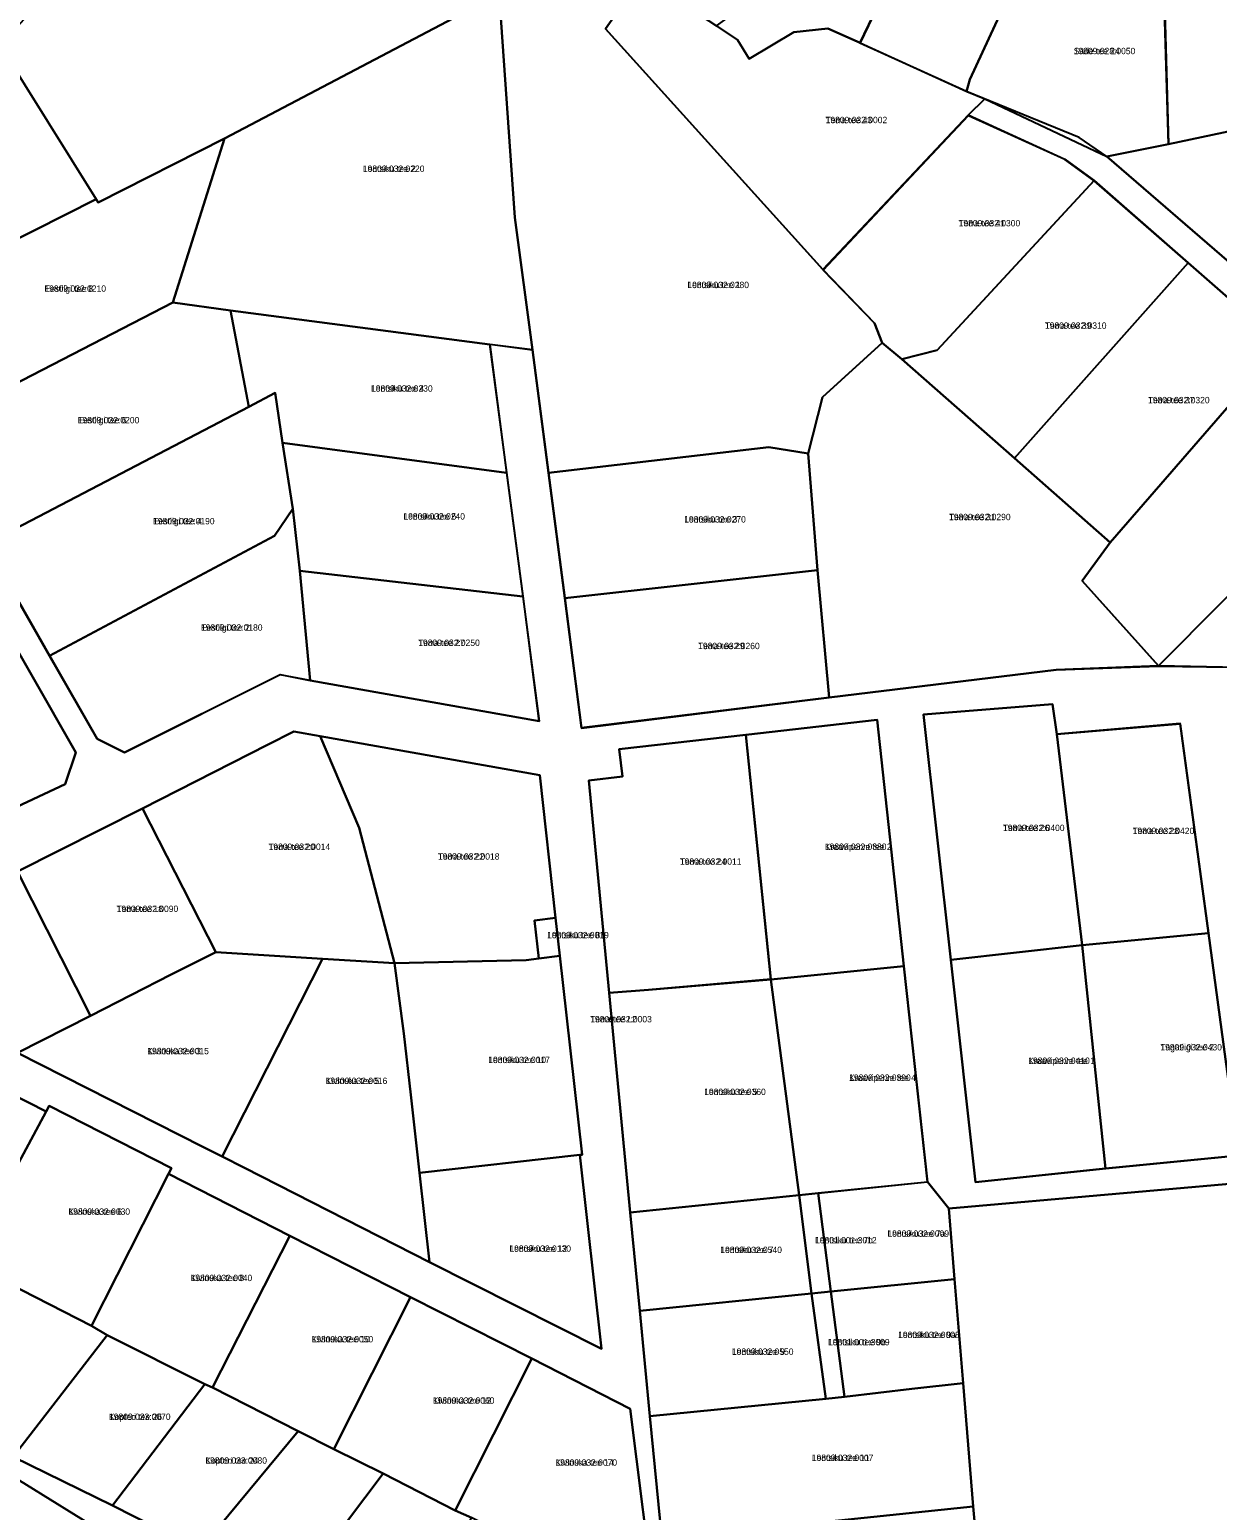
# Model space of a CAD drawing. Extents: x 516875 to 535633, y 6574491 to 6593094.
# Drawn here: x 521368.5 to 521648.2, y 6588311.2 to 6588659.7 of the extents above; entities that cross this region are included whole.
import ezdxf

# ---------------------------------------------------------------- set-up
doc = ezdxf.new("R2010")
doc.units = 0
for name, color, linetype in [('L_AADRESS', 7, 'Continuous'), ('PIIR', 7, 'Continuous'), ('TUNNUS', 7, 'Continuous')]:
    doc.layers.add(name, color=color, linetype=linetype)

msp = doc.modelspace()

# ---------------------------------------------------------------- linework, layer by layer
at = {"layer": 'PIIR'}
for points in [[(521413.29, 6588714.19), (521418.94, 6588723.37), (521421.81, 6588728.14), (521449.85, 6588699.7), (521477.52, 6588688.69), (521479.07, 6588668.07), (521414.43, 6588634.08), (521384.67, 6588618.99), (521384.19, 6588619.81), (521361.62, 6588655.9)], [(521555.15, 6588700.16), (521579.64, 6588689.1), (521564.06, 6588656.54), (521556.42, 6588659.95), (521548.45, 6588659.06), (521537.94, 6588652.79), (521535.14, 6588657.27), (521530.2, 6588660.59), (521540.06, 6588667.73)], [(521486.87, 6588584.33), (521482.75, 6588615.48), (521479.07, 6588668.07), (521477.52, 6588688.69), (521494.97, 6588682.17), (521512.17, 6588671.42), (521504.07, 6588659.84), (521555.23, 6588603.22), (521567.46, 6588590.61), (521569.21, 6588585.96), (521555.19, 6588573.17), (521551.79, 6588559.93), (521542.52, 6588561.47), (521490.64, 6588555.41)], [(521579.64, 6588689.1), (521603.77, 6588677.97), (521589.89, 6588647.97), (521589.09, 6588645.14), (521564.01, 6588656.5)], [(521589.89, 6588647.97), (521603.77, 6588677.97), (521616, 6588673.19), (521635.59, 6588669.68), (521636.61, 6588632.74), (521622.12, 6588629.84), (521615.58, 6588634.3), (521589.09, 6588645.14)], [(521635.57, 6588669.71), (521645.98, 6588675.4), (521650.36, 6588677.81), (521657.98, 6588660.01), (521686.54, 6588663.79), (521687.16, 6588643.42), (521662.53, 6588638.23), (521636.65, 6588632.7)], [(521512.66, 6588672.12), (521530.2, 6588660.59), (521535.14, 6588657.27), (521537.94, 6588652.79), (521548.45, 6588659.06), (521556.42, 6588659.95), (521564.06, 6588656.54), (521589.16, 6588645.12), (521593.39, 6588643.38), (521589.51, 6588639.54), (521555.23, 6588603.22), (521504.07, 6588659.84)], [(521402.26, 6588595.47), (521414.43, 6588634.08), (521479.07, 6588668.07), (521482.75, 6588615.48), (521486.87, 6588584.33), (521476.87, 6588585.59), (521415.82, 6588593.57)], [(521384.19, 6588619.81), (521304.11, 6588579.39), (521302.8, 6588580.8), (521290.73, 6588597.7), (521361.62, 6588655.9)], [(521636.61, 6588632.74), (521662.53, 6588638.23), (521687.16, 6588643.42), (521692.7, 6588638.85), (521675.78, 6588636.22), (521675.71, 6588630.06), (521652.69, 6588603.5), (521622.12, 6588629.84)], [(521573.84, 6588582.13), (521569.21, 6588585.96), (521567.46, 6588590.61), (521555.31, 6588603.1), (521589.52, 6588639.46), (521612.21, 6588629.17), (521619.16, 6588624.15), (521582.14, 6588584.26)], [(521336.74, 6588561.89), (521326.71, 6588564.3), (521315.63, 6588566.96), (521304.11, 6588579.39), (521384.19, 6588619.81), (521384.67, 6588618.99), (521414.43, 6588634.08), (521402.26, 6588595.47), (521343.03, 6588564.98)], [(521573.84, 6588582.13), (521582.14, 6588584.26), (521619.16, 6588624.15), (521641.26, 6588604.83), (521600.35, 6588558.85)], [(521600.35, 6588558.85), (521641.26, 6588604.83), (521663.3, 6588585.55), (521622.88, 6588538.98)], [(521343.03, 6588564.98), (521402.26, 6588595.47), (521415.82, 6588593.57), (521420.15, 6588570.94), (521358.14, 6588538.6)], [(521426.33, 6588574.19), (521420.15, 6588570.94), (521415.82, 6588593.57), (521476.87, 6588585.59), (521480.82, 6588555.43), (521428.08, 6588562.47)], [(521553.97, 6588532.47), (521551.79, 6588559.93), (521555.19, 6588573.17), (521569.21, 6588585.96), (521573.84, 6588582.13), (521600.35, 6588558.85), (521622.88, 6588538.98), (521616.28, 6588529.95), (521634.3, 6588509.94), (521610.2, 6588509), (521556.78, 6588502.53)], [(521616.28, 6588529.95), (521622.88, 6588538.98), (521663.3, 6588585.55), (521686.13, 6588565.57), (521664.39, 6588540.27), (521634.3, 6588509.94)], [(521358.14, 6588538.6), (521420.15, 6588570.94), (521426.33, 6588574.19), (521428.08, 6588562.47), (521430.45, 6588546.91), (521426.17, 6588540.56), (521373.18, 6588512.37)], [(521676.85, 6588510.03), (521656.9, 6588509.51), (521634.3, 6588509.94), (521664.39, 6588540.27), (521686.13, 6588565.57), (521711.04, 6588543.8), (521682.19, 6588513.73)], [(521430.45, 6588546.91), (521428.08, 6588562.47), (521480.82, 6588555.43), (521484.65, 6588526.32), (521432.15, 6588532.34)], [(521490.64, 6588555.41), (521542.52, 6588561.47), (521551.79, 6588559.93), (521553.97, 6588532.47), (521494.53, 6588525.92)], [(521384.42, 6588492.79), (521373.18, 6588512.37), (521426.17, 6588540.56), (521430.45, 6588546.91), (521432.15, 6588532.34), (521434.59, 6588506.53), (521427.53, 6588507.89), (521390.87, 6588489.57)], [(521432.15, 6588532.34), (521484.65, 6588526.32), (521488.51, 6588496.98), (521434.59, 6588506.53)], [(521494.53, 6588525.92), (521553.97, 6588532.47), (521556.78, 6588502.53), (521498.48, 6588495.36)], [(521324.69, 6588511.99), (521330.6, 6588513.8), (521336.2, 6588511.76), (521358.78, 6588525.59), (521379.42, 6588489.59), (521376.89, 6588482.13), (521349.03, 6588469.11)], [(521578.99, 6588498.53), (521585.38, 6588440.81), (521591.22, 6588388.52), (521621.86, 6588391.71), (521653.14, 6588394.78), (521646.07, 6588447.07), (521639.38, 6588496.37), (521610.38, 6588493.89), (521609.37, 6588500.98)], [(521609.35, 6588500.97), (521610.36, 6588493.91), (521616.34, 6588444.25), (521585.38, 6588440.81), (521578.99, 6588498.53)], [(521537.13, 6588493.76), (521568.05, 6588497.29), (521574.35, 6588439.3), (521543.04, 6588436.19)], [(521610.36, 6588493.91), (521639.38, 6588496.34), (521646.04, 6588447.07), (521616.34, 6588444.25)], [(521323.78, 6588440.31), (521365.66, 6588418.95), (521409.32, 6588396.82), (521413.81, 6588394.55), (521419.09, 6588391.88), (521462.63, 6588369.68), (521503.15, 6588349.24), (521498.02, 6588394.94), (521498.57, 6588394.91), (521494.88, 6588427.74), (521493.33, 6588441.71), (521492.34, 6588450.66), (521488.6, 6588484.27), (521436.92, 6588493.42), (521430.73, 6588494.52), (521424.55, 6588491.36), (521395.11, 6588476.42), (521365.67, 6588461.55)], [(521395.11, 6588476.42), (521424.55, 6588491.36), (521430.73, 6588494.52), (521436.92, 6588493.42), (521446.11, 6588471.83), (521454.43, 6588440.02), (521437.47, 6588441.06), (521412.32, 6588442.6)], [(521436.92, 6588493.42), (521488.6, 6588484.27), (521492.34, 6588450.66), (521487.39, 6588450.02), (521488.39, 6588441.08), (521485.39, 6588440.69), (521454.43, 6588440.02), (521446.11, 6588471.83)], [(521500.15, 6588482.97), (521508.09, 6588483.95), (521507.31, 6588490.34), (521537.16, 6588493.73), (521543.05, 6588436.21), (521514.23, 6588433.75), (521504.93, 6588433.03)], [(521365.67, 6588461.55), (521395.11, 6588476.42), (521412.32, 6588442.6), (521401.85, 6588437.31), (521382.85, 6588427.66)], [(521382.85, 6588427.66), (521365.66, 6588418.95), (521323.78, 6588440.31), (521365.67, 6588461.55)], [(521487.39, 6588450.02), (521492.34, 6588450.66), (521493.33, 6588441.71), (521488.39, 6588441.08)], [(521616.34, 6588444.25), (521646.04, 6588447.07), (521653.1, 6588394.78), (521621.84, 6588391.69)], [(521365.66, 6588418.95), (521382.85, 6588427.66), (521401.85, 6588437.31), (521412.32, 6588442.6), (521437.47, 6588441.06), (521413.81, 6588394.55), (521409.32, 6588396.82)], [(521585.38, 6588440.81), (521616.34, 6588444.25), (521621.84, 6588391.69), (521591.18, 6588388.5)], [(521437.47, 6588441.06), (521454.43, 6588440.02), (521456.63, 6588423.5), (521458.23, 6588409.01), (521460.27, 6588390.65), (521462.63, 6588369.68), (521419.09, 6588391.88), (521413.81, 6588394.55)], [(521454.43, 6588440.02), (521485.39, 6588440.69), (521488.39, 6588441.08), (521493.33, 6588441.71), (521494.88, 6588427.74), (521498.57, 6588394.91), (521498.02, 6588394.94), (521460.27, 6588390.65), (521458.23, 6588409.01), (521456.63, 6588423.5)], [(521543.04, 6588436.19), (521574.35, 6588439.3), (521579.88, 6588388.5), (521554.14, 6588385.88), (521549.7, 6588385.41)], [(521504.96, 6588433), (521514.21, 6588433.77), (521543.04, 6588436.19), (521549.7, 6588385.41), (521509.93, 6588381.33)], [(521320.13, 6588386.78), (521338.31, 6588422.41), (521372.42, 6588405.09), (521353.4, 6588369.85)], [(521364.61, 6588323.87), (521355.48, 6588328.35), (521318.72, 6588351.51), (521285.85, 6588399.49), (521285.39, 6588404.51), (521320.13, 6588386.78), (521353.4, 6588369.85), (521383.07, 6588354.68), (521386.74, 6588352.5)], [(521353.4, 6588369.85), (521372.42, 6588405.09), (521373.15, 6588406.46), (521401.93, 6588391.79), (521401.19, 6588390.42), (521383.07, 6588354.68)], [(521460.27, 6588390.65), (521498.02, 6588394.94), (521503.15, 6588349.24), (521462.63, 6588369.68)], [(521383.07, 6588354.68), (521401.19, 6588390.42), (521429.77, 6588375.89), (521411.59, 6588340.18), (521409.79, 6588340.96), (521386.74, 6588352.5)], [(521554.14, 6588385.88), (521579.91, 6588388.54), (521584.92, 6588382.26), (521586.28, 6588365.65), (521557.16, 6588362.72)], [(521611.88, 6588234.23), (521596.92, 6588242.31), (521590.65, 6588312.15), (521588.28, 6588341.15), (521586.28, 6588365.65), (521584.92, 6588382.26), (521663.55, 6588389.16), (521668.37, 6588389.58), (521695.06, 6588375.17), (521739.03, 6588351.41), (521660.34, 6588207.31), (521660.3, 6588207.32), (521657.67, 6588207.99), (521654.73, 6588209.24), (521633.08, 6588222.19)], [(521509.93, 6588381.33), (521549.7, 6588385.41), (521552.62, 6588362.26), (521512.16, 6588358.19)], [(521552.62, 6588362.26), (521549.7, 6588385.41), (521554.14, 6588385.88), (521557.16, 6588362.72)], [(521411.59, 6588340.18), (521429.77, 6588375.89), (521458.21, 6588361.42), (521440.11, 6588325.68), (521431.72, 6588329.86)], [(521555.95, 6588337.47), (521552.62, 6588362.26), (521557.16, 6588362.72), (521560.37, 6588337.96)], [(521557.16, 6588362.72), (521586.28, 6588365.65), (521588.28, 6588341.15), (521576.21, 6588339.82), (521560.37, 6588337.96)], [(521440.11, 6588325.68), (521458.21, 6588361.42), (521486.78, 6588346.95), (521468.72, 6588311.25), (521451.74, 6588319.93)], [(521512.16, 6588358.19), (521552.62, 6588362.26), (521555.95, 6588337.47), (521514.54, 6588333.43)], [(521364.61, 6588323.87), (521386.74, 6588352.5), (521409.79, 6588340.96), (521388.06, 6588312.36)], [(521468.72, 6588311.25), (521486.78, 6588346.95), (521509.89, 6588335.14), (521515.92, 6588287.13), (521494.35, 6588298.36), (521472.65, 6588309.47)], [(521388.06, 6588312.36), (521409.79, 6588340.96), (521411.59, 6588340.18), (521431.72, 6588329.86), (521408.61, 6588301.99)], [(521514.55, 6588333.45), (521555.95, 6588337.47), (521560.37, 6588337.96), (521576.21, 6588339.82), (521588.28, 6588341.15), (521590.65, 6588312.15), (521579.38, 6588310.99), (521528.73, 6588305.77), (521517.32, 6588304.6)], [(521408.61, 6588301.99), (521431.72, 6588329.86), (521440.11, 6588325.68), (521451.74, 6588319.93), (521429.91, 6588290.99)], [(521384.51, 6588306.87), (521384.95, 6588304.15), (521371, 6588285.34), (521345.87, 6588299.49), (521362.2, 6588320.69)], [(521429.91, 6588290.99), (521451.74, 6588319.93), (521468.72, 6588311.25), (521472.65, 6588309.47), (521450.9, 6588280.42)], [(521528.73, 6588305.77), (521579.38, 6588310.99), (521590.65, 6588312.15), (521596.92, 6588242.31), (521591.18, 6588245.45), (521565.41, 6588259.95), (521544.23, 6588271.82), (521532.15, 6588278.52)]]:
    msp.add_lwpolyline(points, close=True, dxfattribs=at)
for points in [[(521663.3, 6588585.53), (521641.25, 6588604.8), (521619.16, 6588624.1), (521612.2, 6588629.15), (521589.51, 6588639.54), (521593.39, 6588643.38), (521622.12, 6588629.84), (521652.69, 6588603.5)], [(521358.17, 6588538.6), (521373.19, 6588512.41), (521384.41, 6588492.77), (521390.88, 6588489.55), (521427.5, 6588507.92), (521434.58, 6588506.51), (521488.51, 6588496.95), (521484.69, 6588526.35), (521480.86, 6588555.45), (521476.84, 6588585.63), (521486.9, 6588584.31), (521490.66, 6588555.44), (521494.55, 6588525.96), (521498.46, 6588495.32), (521556.78, 6588502.53), (521610.2, 6588509.04), (521634.32, 6588509.92), (521656.89, 6588509.55)], [(521349.03, 6588469.11), (521376.89, 6588482.13), (521379.42, 6588489.59), (521358.78, 6588525.59)], [(521663.55, 6588389.16), (521584.92, 6588382.26), (521579.91, 6588388.54), (521574.37, 6588439.31), (521568.04, 6588497.26), (521537.16, 6588493.73), (521507.31, 6588490.34), (521508.09, 6588483.95), (521500.15, 6588482.97), (521504.93, 6588433.03), (521509.94, 6588381.35), (521512.17, 6588358.21), (521514.55, 6588333.45), (521517.32, 6588304.6)], [(521515.92, 6588287.13), (521509.89, 6588335.14), (521486.78, 6588346.95), (521458.21, 6588361.42), (521429.77, 6588375.89), (521401.19, 6588390.42), (521401.93, 6588391.79), (521373.15, 6588406.46), (521372.42, 6588405.09), (521338.31, 6588422.41)], [(521328.95, 6588293.9), (521355.48, 6588328.35), (521364.61, 6588323.87), (521388.06, 6588312.36), (521408.61, 6588301.99)], [(521384.51, 6588306.87), (521362.2, 6588320.69), (521345.87, 6588299.49)]]:
    msp.add_lwpolyline(points, dxfattribs=at)

# ---------------------------------------------------------------- texts
at = {"layer": 'L_AADRESS'}
for s, p in [('Säde tee 24', (521614.33, 6588653.9)), ('Terra tee 43', (521555.92, 6588637.67)), ('Lontsiku tee 2', (521446.97, 6588626.2)), ('Terra tee 41', (521587.23, 6588613.39)), ('Eestiigi tee 8', (521372, 6588597.99)), ('Lontsiku tee 1', (521523.37, 6588598.86)), ('Terra tee 39', (521607.55, 6588589.29)), ('Lontsiku tee 4', (521448.9, 6588574.5)), ('Terra tee 37', (521631.82, 6588571.76)), ('Eestiigi tee 6', (521379.84, 6588567.04)), ('Eestiigi tee 4', (521397.56, 6588543.28)), ('Lontsiku tee 6', (521456.51, 6588544.4)), ('Lontsiku tee 3', (521522.63, 6588543.7)), ('Terra tee 31', (521584.97, 6588544.25)), ('Eestiigi tee 2', (521408.85, 6588518.24)), ('Terra tee 27', (521460, 6588514.66)), ('Terra tee 29', (521525.9, 6588513.91)), ('Terra tee 26', (521597.67, 6588471.1)), ('Terra tee 28', (521628.2, 6588470.39)), ('Terra tee 20', (521424.77, 6588466.66)), ('Kraaviperve tee 2', (521555.74, 6588466.67)), ('Terra tee 22', (521464.63, 6588464.38)), ('Terra tee 24', (521521.6, 6588463.17)), ('Terra tee 18', (521389, 6588452.06)), ('Lontsiku tee 8', (521490.36, 6588445.87)), ('Terra tee L2', (521500.5, 6588426.08)), ('Kivinuka tee 3', (521396.22, 6588418.58)), ('Tagatiigi tee 2', (521634.72, 6588419.48)), ('Lontsiku tee 10', (521476.5, 6588416.5)), ('Kraaviperve tee 1', (521603.61, 6588416.31)), ('Kivinuka tee 5', (521438.22, 6588411.57)), ('Kraaviperve tee 4', (521561.46, 6588412.32)), ('Lontsiku tee 5', (521527.33, 6588408.99)), ('Kivinuka tee 6', (521377.66, 6588380.8)), ('Lontsiku tee 7a', (521570.47, 6588375.63)), ('Lontsiku tee 12', (521481.47, 6588372.09)), ('Lontsiku tee 7', (521531.13, 6588371.8)), ('Lontsiku tee 7b', (521553.43, 6588374.07)), ('Kivinuka tee 8', (521406.42, 6588365.2)), ('Kivinuka tee 10', (521434.9, 6588350.78)), ('Lontsiku tee 9a', (521572.99, 6588351.8)), ('Lontsiku tee 9', (521533.86, 6588347.85)), ('Lontsiku tee 9b', (521556.49, 6588350.09)), ('Kivinuka tee 12', (521463.45, 6588336.36)), ('Kopteri tee 26', (521387.2, 6588332.53)), ('Lontsiku tee 11', (521552.67, 6588322.88)), ('Kopteri tee 24', (521409.89, 6588322.23)), ('Kivinuka tee 14', (521492.32, 6588321.76))]:
    msp.add_text(s, height=1.5, dxfattribs=at).set_placement(p)
at = {"layer": 'TUNNUS'}
for s, p in [('19809:028:0050', (521614.33, 6588653.9)), ('19809:032:0002', (521555.92, 6588637.67)), ('19809:032:0220', (521446.97, 6588626.2)), ('19809:032:0300', (521587.23, 6588613.39)), ('19809:032:0210', (521372, 6588597.99)), ('19809:032:0280', (521523.37, 6588598.86)), ('19809:032:0310', (521607.55, 6588589.29)), ('19809:032:0230', (521448.9, 6588574.5)), ('19809:032:0320', (521631.82, 6588571.76)), ('19809:032:0200', (521379.84, 6588567.04)), ('19809:032:0190', (521397.56, 6588543.28)), ('19809:032:0240', (521456.51, 6588544.4)), ('19809:032:0270', (521522.63, 6588543.7)), ('19809:032:0290', (521584.97, 6588544.25)), ('19809:032:0180', (521408.85, 6588518.24)), ('19809:032:0250', (521460, 6588514.66)), ('19809:032:0260', (521525.9, 6588513.91)), ('19809:032:0400', (521597.67, 6588471.1)), ('19809:032:0420', (521628.2, 6588470.39)), ('19809:032:0014', (521424.77, 6588466.66)), ('19809:032:0380', (521555.74, 6588466.67)), ('19809:032:0018', (521464.63, 6588464.38)), ('19809:032:0011', (521521.6, 6588463.17)), ('19809:032:0090', (521389, 6588452.06)), ('19809:032:0019', (521490.36, 6588445.87)), ('19809:032:0003', (521500.5, 6588426.08)), ('19809:032:0015', (521396.22, 6588418.58)), ('19809:032:0430', (521634.72, 6588419.48)), ('19809:032:0017', (521476.5, 6588416.5)), ('19809:032:0410', (521603.61, 6588416.31)), ('19809:032:0016', (521438.22, 6588411.57)), ('19809:032:0390', (521561.46, 6588412.32)), ('19809:032:0360', (521527.33, 6588408.99)), ('19809:032:0030', (521377.66, 6588380.8)), ('19809:032:0009', (521570.47, 6588375.63)), ('19809:032:0130', (521481.47, 6588372.09)), ('19809:032:0540', (521531.13, 6588371.8)), ('19801:001:3012', (521553.43, 6588374.07)), ('19809:032:0040', (521406.42, 6588365.2)), ('19809:032:0050', (521434.9, 6588350.78)), ('19809:032:0008', (521572.99, 6588351.8)), ('19809:032:0550', (521533.86, 6588347.85)), ('19801:001:3009', (521556.49, 6588350.09)), ('19809:032:0060', (521463.45, 6588336.36)), ('19809:033:0070', (521387.2, 6588332.53)), ('19809:032:0007', (521552.67, 6588322.88)), ('19809:033:0080', (521409.89, 6588322.23)), ('19809:032:0070', (521492.32, 6588321.76))]:
    msp.add_text(s, height=1.5, dxfattribs=at).set_placement(p)

doc.saveas('drawing.dxf')
